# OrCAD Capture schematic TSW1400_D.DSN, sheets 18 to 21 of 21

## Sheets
18 FPGA Power: size B; title: FPGA Power
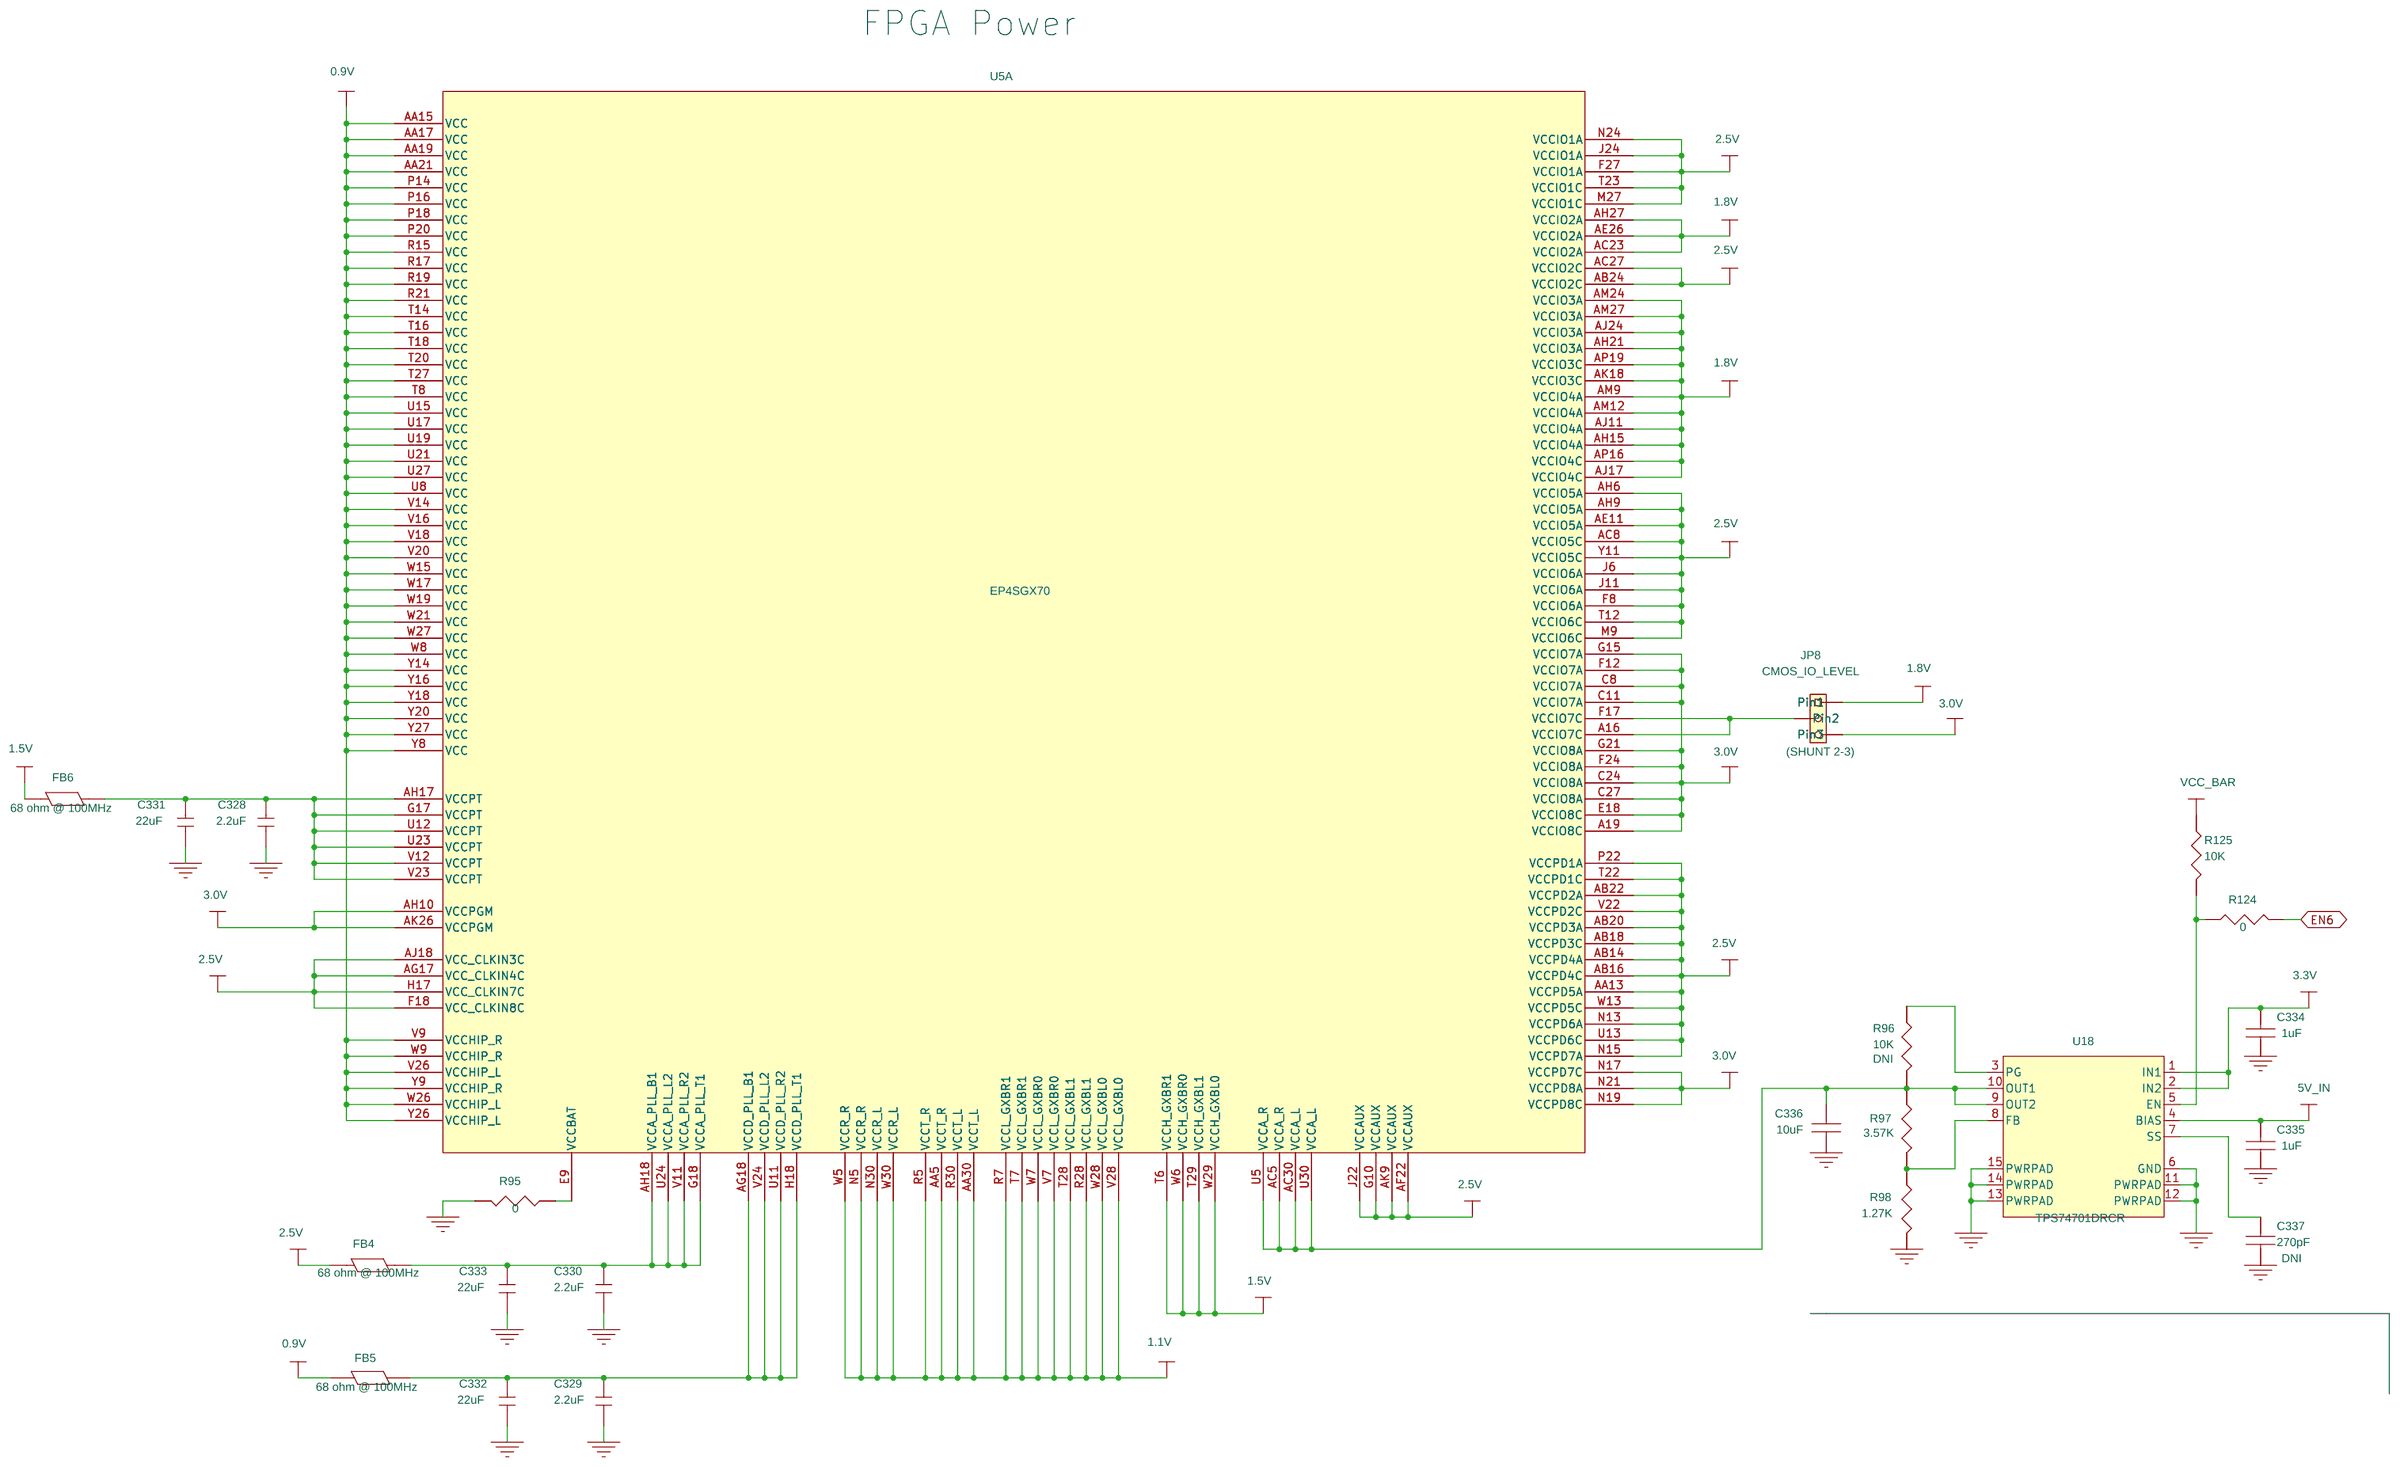
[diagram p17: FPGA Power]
19 FPGA Ground: size B; title: FPGA Ground
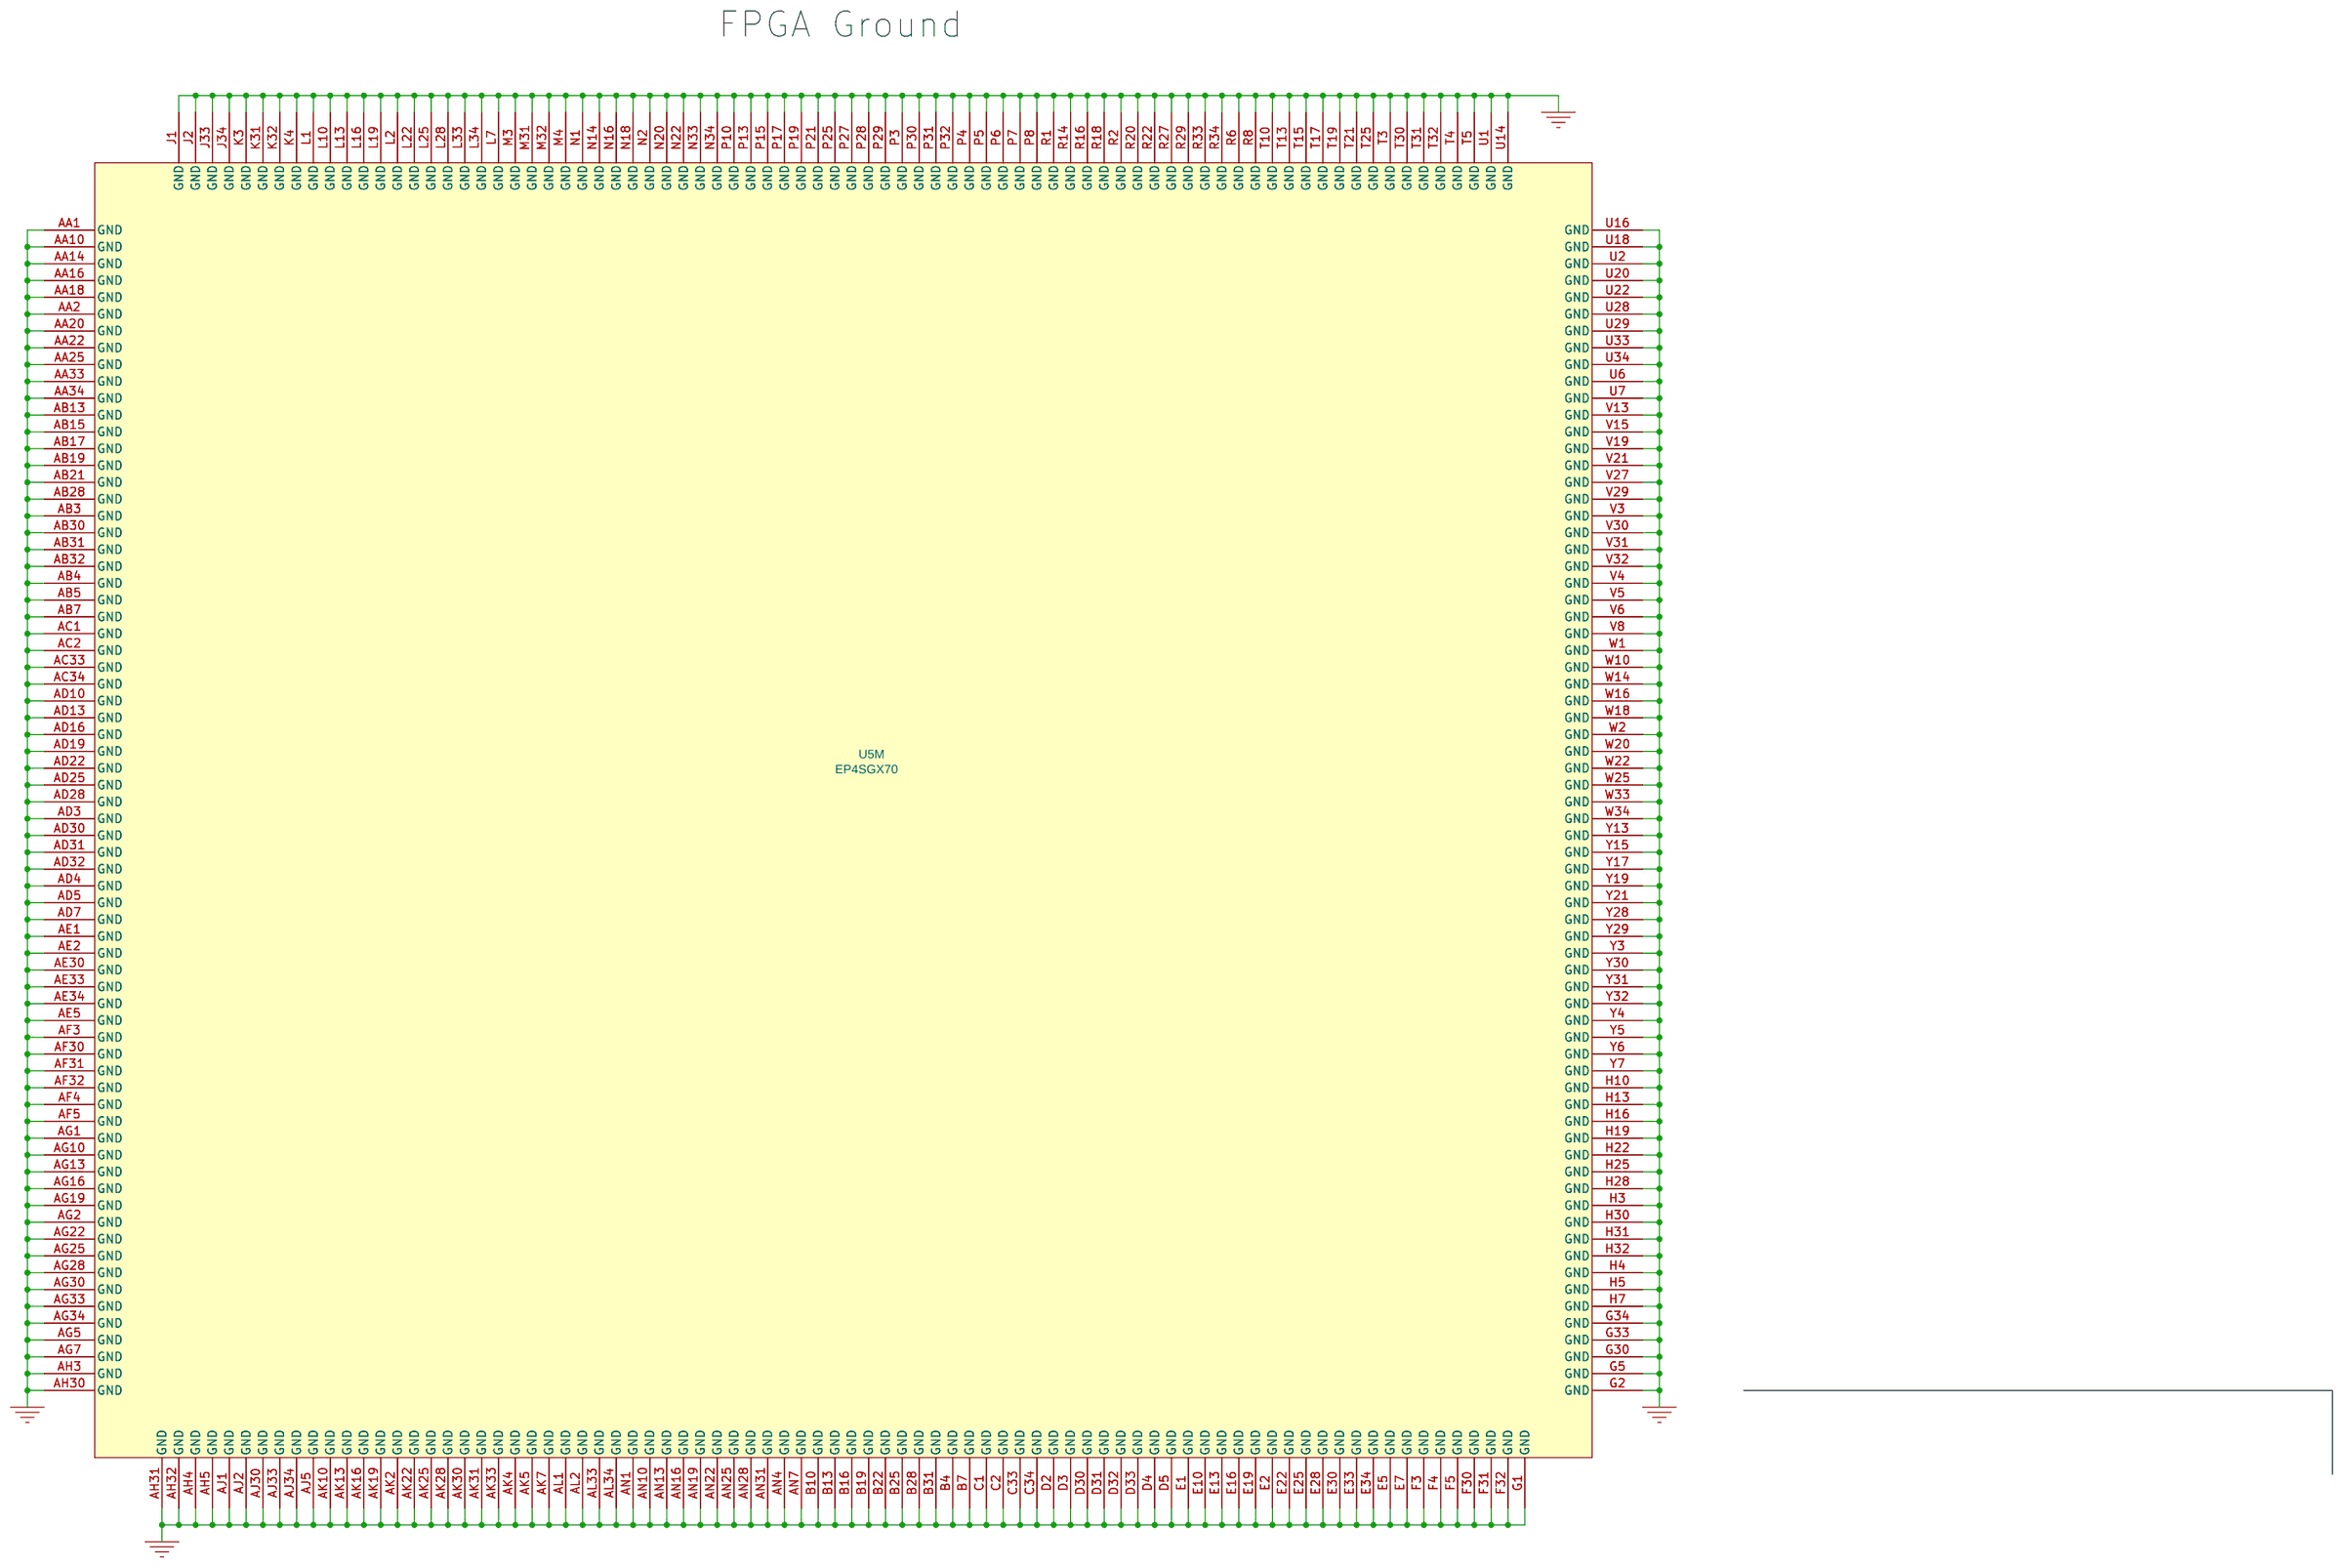
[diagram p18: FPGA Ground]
20 FPGA Decoupling: size B; title: FPGA Decoupling
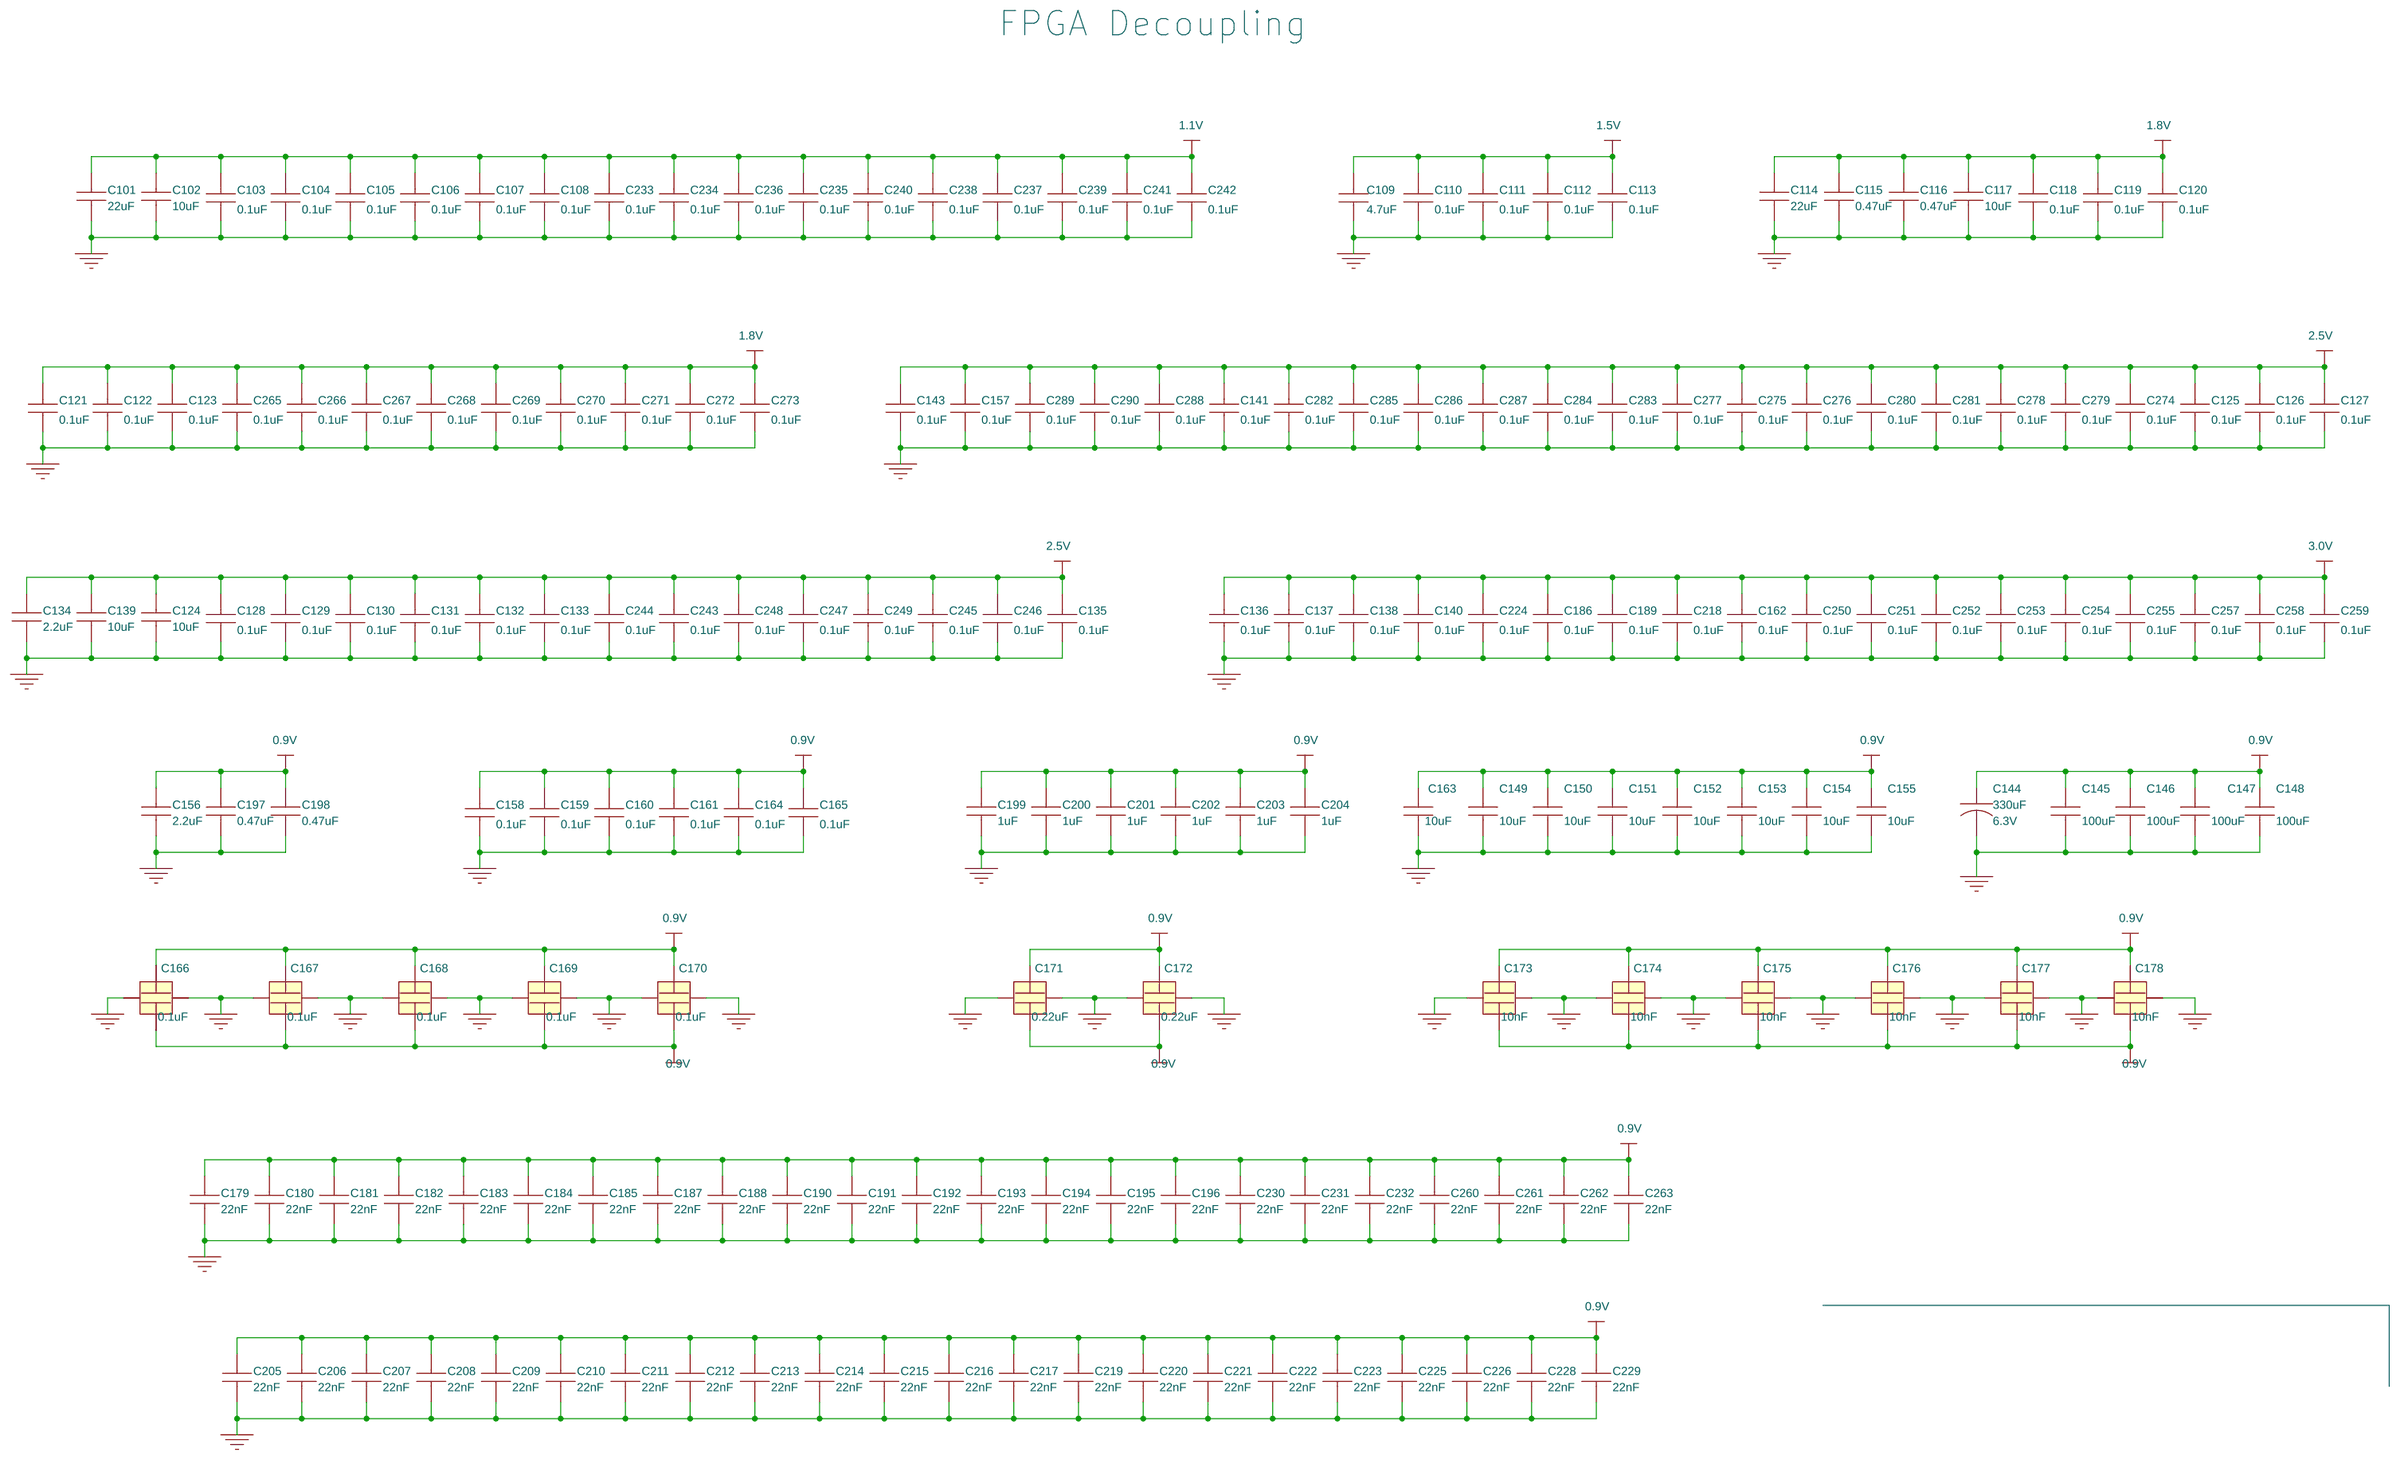
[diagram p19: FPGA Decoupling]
21 FPGA Configuration: size B; title: FPGA Configuration
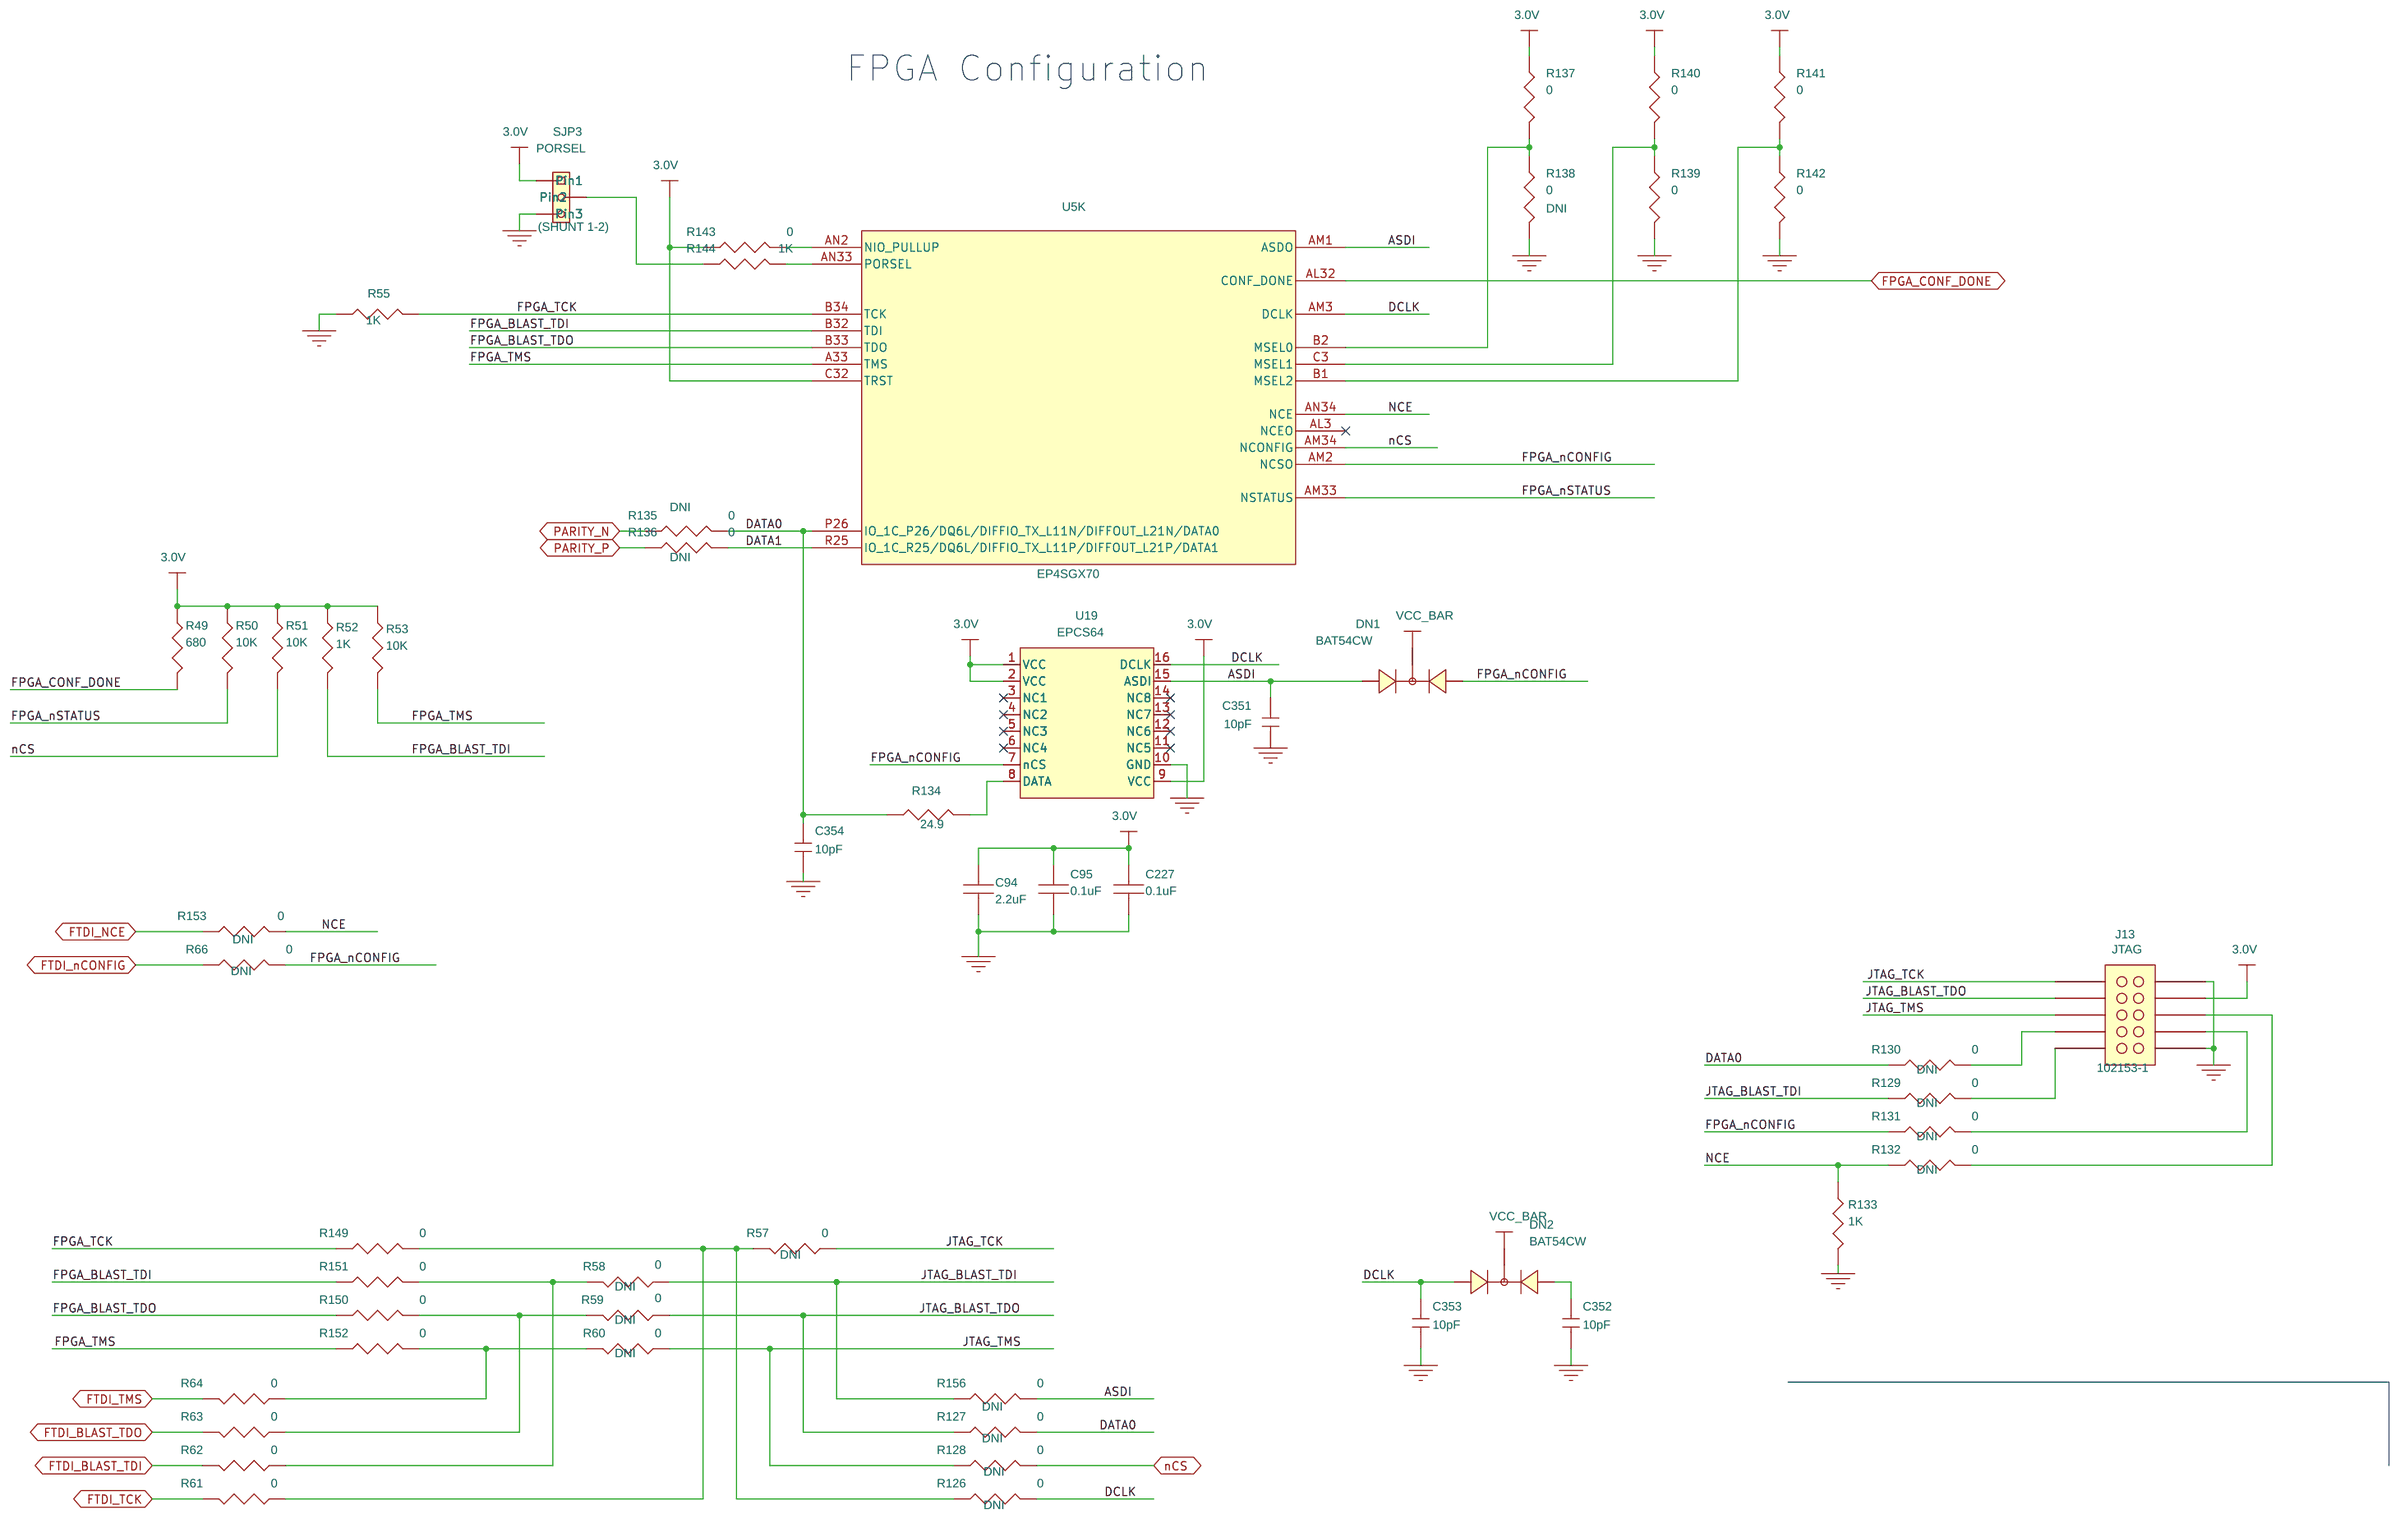
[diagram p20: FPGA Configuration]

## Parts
sheet Bank6
U5  EP4SGX70  [BGA_1152_39]  (sections A,B,C,D,E,F,G,H,I,J,K,L,M,N)
sheet FPGA Configuration
C94  2.2uF  [0603]
C95  0.1uF  [0402]
C227  0.1uF  [0402]
C351  10pF  [0402]
C352  10pF  [0402]
C353  10pF  [0402]
C354  10pF  [0402]
DN1  BAT54CW  [SOT_323]
DN2  BAT54CW  [SOT_323]
J13  102153-1  [CON_THVT_2x5_100_M]
R49  680  [0402]
R50  10K  [0402]
R51  10K  [0402]
R52  1K  [0402]
R53  10K  [0402]
R55  1K  [0402]
R57  0  [0402]
R58  0  [0402]
R59  0  [0402]
R60  0  [0402]
R61  0  [0402]
R62  0  [0402]
R63  0  [0402]
R64  0  [0402]
R66  0  [0402]
R126  0  [0402]
R127  0  [0402]
R128  0  [0402]
R129  0  [0402]
R130  0  [0402]
R131  0  [0402]
R132  0  [0402]
R133  1K  [0402]
R134  24.9  [0402]
R135  0  [0201]
R136  0  [0201]
R137  0  [0402]
R138  0  [0402]
R139  0  [0402]
R140  0  [0402]
R141  0  [0402]
R142  0  [0402]
R143  0  [0402]
R144  1K  [0402]
R149  0  [0402]
R150  0  [0402]
R151  0  [0402]
R152  0  [0402]
R153  0  [0402]
R156  0  [0402]
SJP3  SOLDER JUMPER, 0603  [SMD_JUMPER_1x3]
U19  EPCS64  [SOIC_16_410X299_50]
Z_SH-J3  SHUNT-JUMPER-0603  [0603]
sheet FPGA Decoupling
C101  22uF  [1210]
C102  10uF  [0603]
C103  0.1uF  [0201]
C104  0.1uF  [0201]
C105  0.1uF  [0201]
C106  0.1uF  [0201]
C107  0.1uF  [0201]
C108  0.1uF  [0201]
C109  4.7uF  [0603]
C110  0.1uF  [0201]
C111  0.1uF  [0201]
C112  0.1uF  [0201]
C113  0.1uF  [0201]
C114  22uF  [1210]
C115  0.47uF  [0402]
C116  0.47uF  [0402]
C117  10uF  [0603]
C118  0.1uF  [0201]
C119  0.1uF  [0201]
C120  0.1uF  [0201]
C121  0.1uF  [0201]
C122  0.1uF  [0201]
C123  0.1uF  [0201]
C124  10uF  [0603]
C125  0.1uF  [0201]
C126  0.1uF  [0201]
C127  0.1uF  [0201]
C128  0.1uF  [0201]
C129  0.1uF  [0201]
C130  0.1uF  [0201]
C131  0.1uF  [0201]
C132  0.1uF  [0201]
C133  0.1uF  [0201]
C134  2.2uF  [0603]
C135  0.1uF  [0201]
C136  0.1uF  [0201]
C137  0.1uF  [0201]
C138  0.1uF  [0201]
C139  10uF  [0603]
C140  0.1uF  [0201]
C141  0.1uF  [0201]
C143  0.1uF  [0201]
C144  330uF  [TANT_D]
C145  100uF  [1210]
C146  100uF  [1210]
C147  100uF  [1210]
C148  100uF  [1210]
C149  10uF  [0603]
C150  10uF  [0603]
C151  10uF  [0603]
C152  10uF  [0603]
C153  10uF  [0603]
C154  10uF  [0603]
C155  10uF  [0603]
C156  2.2uF  [0603]
C157  0.1uF  [0201]
C158  0.1uF  [0201]
C159  0.1uF  [0201]
C160  0.1uF  [0201]
C161  0.1uF  [0201]
C162  0.1uF  [0201]
C163  10uF  [0603]
C164  0.1uF  [0201]
C165  0.1uF  [0201]
C166  0.1uF  [C-0603_X2Y]
C167  0.1uF  [C-0603_X2Y]
C168  0.1uF  [C-0603_X2Y]
C169  0.1uF  [C-0603_X2Y]
C170  0.1uF  [C-0603_X2Y]
C171  0.22uF  [C-0603_X2Y]
C172  0.22uF  [C-0603_X2Y]
C173  10nF  [C-0603_X2Y]
C174  10nF  [C-0603_X2Y]
C175  10nF  [C-0603_X2Y]
C176  10nF  [C-0603_X2Y]
C177  10nF  [C-0603_X2Y]
C178  10nF  [C-0603_X2Y]
C179  22nF  [0201]
C180  22nF  [0201]
C181  22nF  [0201]
C182  22nF  [0201]
C183  22nF  [0201]
C184  22nF  [0201]
C185  22nF  [0201]
C186  0.1uF  [0201]
C187  22nF  [0201]
C188  22nF  [0201]
C189  0.1uF  [0201]
C190  22nF  [0201]
C191  22nF  [0201]
C192  22nF  [0201]
C193  22nF  [0201]
C194  22nF  [0201]
C195  22nF  [0201]
C196  22nF  [0201]
C197  0.47uF  [0402]
C198  0.47uF  [0402]
C199  1uF  [0402]
C200  1uF  [0402]
C201  1uF  [0402]
C202  1uF  [0402]
C203  1uF  [0402]
C204  1uF  [0402]
C205  22nF  [0201]
C206  22nF  [0201]
C207  22nF  [0201]
C208  22nF  [0201]
C209  22nF  [0201]
C210  22nF  [0201]
C211  22nF  [0201]
C212  22nF  [0201]
C213  22nF  [0201]
C214  22nF  [0201]
C215  22nF  [0201]
C216  22nF  [0201]
C217  22nF  [0201]
C218  0.1uF  [0201]
C219  22nF  [0201]
C220  22nF  [0201]
C221  22nF  [0201]
C222  22nF  [0201]
C223  22nF  [0201]
C224  0.1uF  [0201]
C225  22nF  [0201]
C226  22nF  [0201]
C228  22nF  [0201]
C229  22nF  [0201]
C230  22nF  [0201]
C231  22nF  [0201]
C232  22nF  [0201]
C233  0.1uF  [0201]
C234  0.1uF  [0201]
C235  0.1uF  [0201]
C236  0.1uF  [0201]
C237  0.1uF  [0201]
C238  0.1uF  [0201]
C239  0.1uF  [0201]
C240  0.1uF  [0201]
C241  0.1uF  [0201]
C242  0.1uF  [0201]
C243  0.1uF  [0201]
C244  0.1uF  [0201]
C245  0.1uF  [0201]
C246  0.1uF  [0201]
C247  0.1uF  [0201]
C248  0.1uF  [0201]
C249  0.1uF  [0201]
C250  0.1uF  [0201]
C251  0.1uF  [0201]
C252  0.1uF  [0201]
C253  0.1uF  [0201]
C254  0.1uF  [0201]
C255  0.1uF  [0201]
C257  0.1uF  [0201]
C258  0.1uF  [0201]
C259  0.1uF  [0201]
C260  22nF  [0201]
C261  22nF  [0201]
C262  22nF  [0201]
C263  22nF  [0201]
C265  0.1uF  [0201]
C266  0.1uF  [0201]
C267  0.1uF  [0201]
C268  0.1uF  [0201]
C269  0.1uF  [0201]
C270  0.1uF  [0201]
C271  0.1uF  [0201]
C272  0.1uF  [0201]
C273  0.1uF  [0201]
C274  0.1uF  [0201]
C275  0.1uF  [0201]
C276  0.1uF  [0201]
C277  0.1uF  [0201]
C278  0.1uF  [0201]
C279  0.1uF  [0201]
C280  0.1uF  [0201]
C281  0.1uF  [0201]
C282  0.1uF  [0201]
C283  0.1uF  [0201]
C284  0.1uF  [0201]
C285  0.1uF  [0201]
C286  0.1uF  [0201]
C287  0.1uF  [0201]
C288  0.1uF  [0201]
C289  0.1uF  [0201]
C290  0.1uF  [0201]
sheet FPGA Power
C328  2.2uF  [0402]
C329  2.2uF  [0402]
C330  2.2uF  [0402]
C331  22uF  [0603]
C332  22uF  [0603]
C333  22uF  [0603]
C334  1uF  [0603]
C335  1uF  [0603]
C336  10uF  [0603]
C337  270pF  [0603]
FB4  68 ohm @ 100MHz  [1206]
FB5  68 ohm @ 100MHz  [1206]
FB6  68 ohm @ 100MHz  [1206]
JP8  HEADER_1x3_100_430L  [HDR_THVT_1x3_100_M]
R95  0  [0402]
R96  10K  [0603]
R97  3.57K  [0603]
R98  1.27K  [0603]
R124  0  [0603]
R125  10K  [0603]
U18  TPS74701DRCR  [SON_10_124x124_pwrpad]
Z_SH-H3  SHUNT-HEADER

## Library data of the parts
U5 = EP4SGX70F1152_2
C94 C134 C156 = CAP: 2.2uF, +/-10%, 10V, X5R(0603); Mfr_Name: Yageo; Mfr_Part_Number: CC0603KRX5R6BB225; Package: SMD; Terasic_Prt: MCC-2000-YGO; Type: Capacitor
C95 C227 = CAP: Mfr_Name: Murata; Mfr_Part_Number: GRM155R61A104KA01D; Package: SMD; Type: Capacitor
C351-C354 = CAP_0402_10pF: Mfr_Name: Murata
DN1 DN2 = DIODE_DUAL_BAT54CW: Mfr_Name: Diodes Inc.
J13 = Header_2x5_100_1: Mfr_Name: Tyco; TI_SILKTEXT: JTAG
R49 = RES: Mfr_Name: Panasonic; Mfr_Part_Number: ERA-W27J681X; Type: Resistor
R50 R51 R53 = RES: Mfr_Name: Panasonic; Mfr_Part_Number: ERJ-2RKF1002X; Type: Resistor
R52 R55 R133 R144 = RES: Mfr_Name: Panasonic; Mfr_Part_Number: ERJ-2RKF1001X
R57-R60 R138 = Res_0402_Zero: Mfr_Name: Panasonic; Mfr_Part_Number: ERJ-2GE0R00X_DNI; Note: DNI
R61-R64 = Res_0402_Zero: Mfr_Name: Panasonic; Mfr_Part_Number: ERJ-2GE0R00X
R66 R126-R132 R153 R156 = Res_0402_Zero_H: Mfr_Name: Panasonic; Mfr_Part_Number: ERJ-2GE0R00X_DNI; Note: DNI
R134 = Res_0402_24.9_H: Mfr_Name: Panasonic
R135 R136 = Res_0402_Zero_H: Mfr_Name: Panasonic; Mfr_Part_Number: ERJ-1GE0R00C_DNI; Note: DNI
R137 = Res_0402_Zero_DNI: Mfr_Name: Panasonic; Mfr_Part_Number: ERJ-2GE0R00X
R139 R141 = Res_0402_Zero_DNI: Mfr_Name: Panasonic
R95 R140 R142 = Res_0402_Zero: Mfr_Name: Panasonic
R143 = Res_0402_Zero_H: Mfr_Name: Panasonic
R149-R152 = Res_0402_Zero_H: Mfr_Name: Panasonic; Mfr_Part_Number: ERJ-2GE0R00X
SJP3 = JUMPER_SMD_1X3: Note: (SHUNT 1-2); TI_Silktext: PORSEL
U19 = EPCS64: Mfr_Name: Altera
Z_SH-J3 = SHUNT-JUMPER-0603
C101 C114 = CAP: MLCC, 22uF, +/-10%, 10V, X5R(1210); Mfr_Name: Murata; Mfr_Part_Number: GRM32ER61A226KE20L; Package: SMD; Terasic_Prt: M1014; Type: Capacitor
C102 C117 C124 C139 C149-C155 C163 C336 = CAP: Mfr_Name: Murata; Mfr_Part_Number: GRM188R60J106ME47D; TOL: 20%; VOLTAGE: 6.3V
C103-C108 C110-C113 C118-C123 C125-C133 C135-C138 C140 C141 C143 C157-C162 C164 C165 C186 C189 C218 C224 C233-C255 C257-C259 C265-C290 = CAP: Mfr_Name: Murata; Mfr_Part_Number: GRM033R60J104KE19D; Package: SMD; Type: Capacitor
C109 = CAP_NP_0: Mfr_Name: Kemet; Mfr_Part_Number: C0603C475K8PACTU; TOL: 10%; VOLTAGE: 10V
C115 C116 C197 C198 = CAP: Mfr_Name: Murata; Mfr_Part_Number: GRM155F51A474ZE01D
C144 = CAPT: Mfr_Name: Kemet; Mfr_Part_Number: T520D337M006ATE015; Package: SMD; Voltage: 6.3V
C145-C148 = CAP: Mfr_Name: Murata; Mfr_Part_Number: GRM32ER60J107ME20L; TOL: 20%; VOLTAGE: 6.3V
C166-C170 = CAP_X2Y: Mfr_Name: Johanson Dielectrics Inc; Mfr_Part_Number: 100X14W104MV4T; Package: SMD; Type: Capacitor
C171 C172 = CAP_X2Y: X2Y, 0.22uF, +/-20%, 10V, X5R(0603); Mfr_Name: Johanson Dielectrics Inc; Mfr_Part_Number: 160X14X224MV4T; Package: SMD; Terasic_Prt: MP03-16112R; Type: Capacitor
C173-C178 = CAP_X2Y: X2Y, 10nF, +/-20%, 50V, X7R, 0603; Mfr_Name: Johanson Dielectrics Inc; Mfr_Part_Number: 500X14W103MV4T; Package: SMD; Terasic_Prt: M1099; Type: Capacitor
C179-C185 C187 C188 C190-C196 C205-C217 C219-C223 C225 C226 C228-C232 C260-C263 = CAP: Mfr_Name: Murata; Mfr_Part_Number: GRM033R60J223KE01D
C199-C204 = CAP: Mfr_Name: Murata; Mfr_Part_Number: GRM155R61A105KE15D; Tolerance: 10%; Voltage: 10V
C328-C330 = CAP0201: Mfr_Name: Taiyo Yuden; Mfr_Part_Number: JMK105BJ225MV-F; TOL: 20%; VOLTAGE: 6.3V
C331-C333 = CAP0201: Mfr_Name: Taiyo Yuden; Mfr_Part_Number: AMK107BJ226MA-T; TOL: 20%; VOLTAGE: 4V
C334 C335 = CAP_0603_H: Mfr_Name: Murata; Mfr_Part_Number: GRM188R60J105KA01D; Tolerance: 10%; Voltage: 6.3V
C337 = CAP: Mfr_Name: Murata; Mfr_Part_Number: GRM1885C1H271JA01D_DNI; Note: DNI
FB4-FB6 = FERRITE_BEAD: Mfr_Name: Panasonic; Mfr_Part_Number: EXC-ML32A680U
JP8 = JUMPER_1x3_100: Note: (SHUNT 2-3); TI_Silktext: CMOS_IO_LEVEL
R96 = RES: Mfr_Name: Panasonic; Mfr_Part_Number: ERJ-3EKF1002V_DNI; Note: DNI; Type: Resistor
R97 = RES: Mfr_Name: Panasonic; Mfr_Part_Number: ERJ-3EKF3571V; Type: Resistor
R98 = RES: Mfr_Name: Panasonic; Mfr_Part_Number: ERJ-3EKF1271V; Type: Resistor
R124 = RES: Mfr_Name: Panasonic; Mfr_Part_Number: ERJ-3GEY0R00V; Type: Resistor
R125 = Res_0603_10k: Mfr_Name: Panasonic
U18 = TPS74701DRCR
Z_SH-H3 = SHUNT-3PINHEADER

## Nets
0.9V: C144.1(ANODE) C145.1 C146.1 C147.1 C148.1 C149.1 C150.1 C151.1 C152.1 C153.1 C154.1 C155.1 C156.1 C158.2 C159.2 C160.2 C161.2 C163.1 C164.2 C165.2 C166.A C166.B C167.A C167.B C168.A C168.B C169.A C169.B C170.A C170.B C171.A C171.B C172.A C172.B C173.A C173.B C174.A C174.B C175.A C175.B C176.A C176.B C177.A C177.B C178.A C178.B C179.1 C180.1 C181.1 C182.1 C183.1 C184.1 C185.1 C187.1 C188.1 C190.1 C191.1 C192.1 C193.1 C194.1 C195.1 C196.1 C197.1 C198.1 C199.1 C200.1 C201.1 C202.1 C203.1 C204.1 C205.1 C206.1 C207.1 C208.1 C209.1 C210.1 C211.1 C212.1 C213.1 C214.1 C215.1 C216.1 C217.1 C219.1 C220.1 C221.1 C222.1 C223.1 C225.1 C226.1 C228.1 C229.1 C230.1 C231.1 C232.1 C260.1 C261.1 C262.1 C263.1 FB5.1 U5.AA15(VCC) U5.AA17(VCC) U5.AA19(VCC) U5.AA21(VCC) U5.P14(VCC) U5.P16(VCC) U5.P18(VCC) U5.P20(VCC) U5.R15(VCC) U5.R17(VCC) U5.R19(VCC) U5.R21(VCC) U5.T8(VCC) U5.T14(VCC) U5.T16(VCC) U5.T18(VCC) U5.T20(VCC) U5.T27(VCC) U5.U8(VCC) U5.U15(VCC) U5.U17(VCC) U5.U19(VCC) U5.U21(VCC) U5.U27(VCC) U5.V9(VCCHIP_R) U5.V14(VCC) U5.V16(VCC) U5.V18(VCC) U5.V20(VCC) U5.V26(VCCHIP_L) U5.W8(VCC) U5.W9(VCCHIP_R) U5.W15(VCC) U5.W17(VCC) U5.W19(VCC) U5.W21(VCC) U5.W26(VCCHIP_L) U5.W27(VCC) U5.Y8(VCC) U5.Y9(VCCHIP_R) U5.Y14(VCC) U5.Y16(VCC) U5.Y18(VCC) U5.Y20(VCC) U5.Y26(VCCHIP_L) U5.Y27(VCC) ; also on sheet 7 16
1.1V: C101.1 C102.1 C103.2 C104.2 C105.2 C106.2 C107.2 C108.2 C233.2 C234.2 C235.2 C236.2 C237.2 C238.2 C239.2 C240.2 C241.2 C242.2 U5.AA5(VCCT_R) U5.AA30(VCCT_L) U5.N5(VCCR_R) U5.N30(VCCR_L) U5.R5(VCCT_R) U5.R7(VCCL_GXBR1) U5.R28(VCCL_GXBL1) U5.R30(VCCT_L) U5.T7(VCCL_GXBR1) U5.T28(VCCL_GXBL1) U5.V7(VCCL_GXBR0) U5.V28(VCCL_GXBL0) U5.W5(VCCR_R) U5.W7(VCCL_GXBR0) U5.W28(VCCL_GXBL0) U5.W30(VCCR_L) ; also on sheet 16
1.5V: C109.2 C110.2 C111.2 C112.2 C113.2 FB6.1 U5.T6(VCCH_GXBR1) U5.T29(VCCH_GXBL1) U5.W6(VCCH_GXBR0) U5.W29(VCCH_GXBL0) ; also on sheet 16
1.8V: C114.1 C115.1 C116.1 C117.1 C118.2 C119.2 C120.2 C121.2 C122.2 C123.2 C265.2 C266.2 C267.2 C268.2 C269.2 C270.2 C271.2 C272.2 C273.2 JP8.1(Pin1) U5.AC23(VCCIO2A) U5.AE26(VCCIO2A) U5.AH15(VCCIO4A) U5.AH21(VCCIO3A) U5.AH27(VCCIO2A) U5.AJ11(VCCIO4A) U5.AJ17(VCCIO4C) U5.AJ24(VCCIO3A) U5.AK18(VCCIO3C) U5.AM9(VCCIO4A) U5.AM12(VCCIO4A) U5.AM24(VCCIO3A) U5.AM27(VCCIO3A) U5.AP16(VCCIO4C) U5.AP19(VCCIO3C) ; also on sheet 5 6 9 16
2.5V: C124.1 C125.2 C126.2 C127.2 C128.2 C129.2 C130.2 C131.2 C132.2 C133.2 C134.1 C135.2 C139.1 C141.2 C143.2 C157.2 C243.2 C244.2 C245.2 C246.2 C247.2 C248.2 C249.2 C274.2 C275.2 C276.2 C277.2 C278.2 C279.2 C280.2 C281.2 C282.2 C283.2 C284.2 C285.2 C286.2 C287.2 C288.2 C289.2 C290.2 FB4.1 U5.AA13(VCCPD5A) U5.AB14(VCCPD4A) U5.AB16(VCCPD4C) U5.AB18(VCCPD3C) U5.AB20(VCCPD3A) U5.AB22(VCCPD2A) U5.AB24(VCCIO2C) U5.AC8(VCCIO5C) U5.AC27(VCCIO2C) U5.AE11(VCCIO5A) U5.AF22(VCCAUX) U5.AG17(VCC_CLKIN4C) U5.AH6(VCCIO5A) U5.AH9(VCCIO5A) U5.AJ18(VCC_CLKIN3C) U5.AK9(VCCAUX) U5.F8(VCCIO6A) U5.F18(VCC_CLKIN8C) U5.F27(VCCIO1A) U5.G10(VCCAUX) U5.H17(VCC_CLKIN7C) U5.J6(VCCIO6A) U5.J11(VCCIO6A) U5.J22(VCCAUX) U5.J24(VCCIO1A) U5.M9(VCCIO6C) U5.M27(VCCIO1C) U5.N13(VCCPD6A) U5.N15(VCCPD7A) U5.N24(VCCIO1A) U5.P22(VCCPD1A) U5.T12(VCCIO6C) U5.T22(VCCPD1C) U5.T23(VCCIO1C) U5.U13(VCCPD6C) U5.V22(VCCPD2C) U5.W13(VCCPD5C) U5.Y11(VCCIO5C) ; also on sheet 16 17
3.0V: C94.1 C95.1 C136.2 C137.2 C138.2 C140.2 C162.2 C186.2 C189.2 C218.2 C224.2 C227.1 C250.2 C251.2 C252.2 C253.2 C254.2 C255.2 C257.2 C258.2 C259.2 DN1.3 DN2.3 J13.4 JP8.3(Pin3) R49.1 R50.1 R51.1 R52.2 R53.1 R137.1 R140.1 R141.1 R143.1 SJP3.1(Pin1) U5.A19(VCCIO8C) U5.AH10(VCCPGM) U5.AK26(VCCPGM) U5.C8(VCCIO7A) U5.C11(VCCIO7A) U5.C24(VCCIO8A) U5.C27(VCCIO8A) U5.C32(TRST) U5.E18(VCCIO8C) U5.F12(VCCIO7A) U5.F24(VCCIO8A) U5.G15(VCCIO7A) U5.G21(VCCIO8A) U5.N17(VCCPD7C) U5.N19(VCCPD8C) U5.N21(VCCPD8A) U19.1(VCC) U19.2(VCC) U19.9(VCC) ; also on sheet 5 17
3.3V: C334.2 R125.1 U18.1(IN1) U18.2(IN2) ; also on sheet 1 7 17
5V_IN: C335.2 U18.4(BIAS) ; also on sheet 1 16 17
GND: C94.2 C95.2 C101.2 C102.2 C103.1 C104.1 C105.1 C106.1 C107.1 C108.1 C109.1 C110.1 C111.1 C112.1 C113.1 C114.2 C115.2 C116.2 C117.2 C118.1 C119.1 C120.1 C121.1 C122.1 C123.1 C124.2 C125.1 C126.1 C127.1 C128.1 C129.1 C130.1 C131.1 C132.1 C133.1 C134.2 C135.1 C136.1 C137.1 C138.1 C139.2 C140.1 C141.1 C143.1 C144.2(CATHODE) C145.2 C146.2 C147.2 C148.2 C149.2 C150.2 C151.2 C152.2 C153.2 C154.2 C155.2 C156.2 C157.1 C158.1 C159.1 C160.1 C161.1 C162.1 C163.2 C164.1 C165.1 C166.G1 C166.G2 C167.G1 C167.G2 C168.G1 C168.G2 C169.G1 C169.G2 C170.G1 C170.G2 C171.G1 C171.G2 C172.G1 C172.G2 C173.G1 C173.G2 C174.G1 C174.G2 C175.G1 C175.G2 C176.G1 C176.G2 C177.G1 C177.G2 C178.G1 C178.G2 C179.2 C180.2 C181.2 C182.2 C183.2 C184.2 C185.2 C186.1 C187.2 C188.2 C189.1 C190.2 C191.2 C192.2 C193.2 C194.2 C195.2 C196.2 C197.2 C198.2 C199.2 C200.2 C201.2 C202.2 C203.2 C204.2 C205.2 C206.2 C207.2 C208.2 C209.2 C210.2 C211.2 C212.2 C213.2 C214.2 C215.2 C216.2 C217.2 C218.1 C219.2 C220.2 C221.2 C222.2 C223.2 C224.1 C225.2 C226.2 C227.2 C228.2 C229.2 C230.2 C231.2 C232.2 C233.1 C234.1 C235.1 C236.1 C237.1 C238.1 C239.1 C240.1 C241.1 C242.1 C243.1 C244.1 C245.1 C246.1 C247.1 C248.1 C249.1 C250.1 C251.1 C252.1 C253.1 C254.1 C255.1 C257.1 C258.1 C259.1 C260.2 C261.2 C262.2 C263.2 C265.1 C266.1 C267.1 C268.1 C269.1 C270.1 C271.1 C272.1 C273.1 C274.1 C275.1 C276.1 C277.1 C278.1 C279.1 C280.1 C281.1 C282.1 C283.1 C284.1 C285.1 C286.1 C287.1 C288.1 C289.1 C290.1 C328.2 C329.2 C330.2 C331.2 C332.2 C333.2 C334.1 C335.1 C336.2 C337.2 C351.2 C352.2 C353.2 C354.2 J13.2 J13.10 R55.1 R95.2 R98.1 R133.2 R138.2 R139.2 R142.2 SJP3.3(Pin3) U5.AA1(GND) U5.AA2(GND) U5.AA10(GND) U5.AA14(GND) U5.AA16(GND) U5.AA18(GND) U5.AA20(GND) U5.AA22(GND) U5.AA25(GND) U5.AA33(GND) U5.AA34(GND) U5.AB3(GND) U5.AB4(GND) U5.AB5(GND) U5.AB7(GND) U5.AB13(GND) U5.AB15(GND) U5.AB17(GND) U5.AB19(GND) U5.AB21(GND) U5.AB28(GND) U5.AB30(GND) U5.AB31(GND) U5.AB32(GND) U5.AC1(GND) U5.AC2(GND) U5.AC33(GND) U5.AC34(GND) U5.AD3(GND) U5.AD4(GND) U5.AD5(GND) U5.AD7(GND) U5.AD10(GND) U5.AD13(GND) U5.AD16(GND) U5.AD19(GND) U5.AD22(GND) U5.AD25(GND) U5.AD28(GND) U5.AD30(GND) U5.AD31(GND) U5.AD32(GND) U5.AE1(GND) U5.AE2(GND) U5.AE5(GND) U5.AE30(GND) U5.AE33(GND) U5.AE34(GND) U5.AF3(GND) U5.AF4(GND) U5.AF5(GND) U5.AF30(GND) U5.AF31(GND) U5.AF32(GND) U5.AG1(GND) U5.AG2(GND) U5.AG5(GND) U5.AG7(GND) U5.AG10(GND) U5.AG13(GND) U5.AG16(GND) U5.AG19(GND) U5.AG22(GND) U5.AG25(GND) U5.AG28(GND) U5.AG30(GND) U5.AG33(GND) U5.AG34(GND) U5.AH3(GND) U5.AH4(GND) U5.AH5(GND) U5.AH30(GND) U5.AH31(GND) U5.AH32(GND) U5.AJ1(GND) U5.AJ2(GND) U5.AJ5(GND) U5.AJ30(GND) U5.AJ33(GND) U5.AJ34(GND) U5.AK2(GND) U5.AK4(GND) U5.AK5(GND) U5.AK7(GND) U5.AK10(GND) U5.AK13(GND) U5.AK16(GND) U5.AK19(GND) U5.AK22(GND) U5.AK25(GND) U5.AK28(GND) U5.AK30(GND) U5.AK31(GND) U5.AK33(GND) U5.AL1(GND) U5.AL2(GND) U5.AL33(GND) U5.AL34(GND) U5.AN1(GND) U5.AN4(GND) U5.AN7(GND) U5.AN10(GND) U5.AN13(GND) U5.AN16(GND) U5.AN19(GND) U5.AN22(GND) U5.AN25(GND) U5.AN28(GND) U5.AN31(GND) U5.B4(GND) U5.B7(GND) U5.B10(GND) U5.B13(GND) U5.B16(GND) U5.B19(GND) U5.B22(GND) U5.B25(GND) U5.B28(GND) U5.B31(GND) U5.C1(GND) U5.C2(GND) U5.C33(GND) U5.C34(GND) U5.D2(GND) U5.D3(GND) U5.D4(GND) U5.D5(GND) U5.D30(GND) U5.D31(GND) U5.D32(GND) U5.D33(GND) U5.E1(GND) U5.E2(GND) U5.E5(GND) U5.E7(GND) U5.E10(GND) U5.E13(GND) U5.E16(GND) U5.E19(GND) U5.E22(GND) U5.E25(GND) U5.E28(GND) U5.E30(GND) U5.E33(GND) U5.E34(GND) U5.F3(GND) U5.F4(GND) U5.F5(GND) U5.F30(GND) U5.F31(GND) U5.F32(GND) U5.G1(GND) U5.G2(GND) U5.G5(GND) U5.G30(GND) U5.G33(GND) U5.G34(GND) U5.H3(GND) U5.H4(GND) U5.H5(GND) U5.H7(GND) U5.H10(GND) U5.H13(GND) U5.H16(GND) U5.H19(GND) U5.H22(GND) U5.H25(GND) U5.H28(GND) U5.H30(GND) U5.H31(GND) U5.H32(GND) U5.J1(GND) U5.J2(GND) U5.J33(GND) U5.J34(GND) U5.K3(GND) U5.K4(GND) U5.K31(GND) U5.K32(GND) U5.L1(GND) U5.L2(GND) U5.L7(GND) U5.L10(GND) U5.L13(GND) U5.L16(GND) U5.L19(GND) U5.L22(GND) U5.L25(GND) U5.L28(GND) U5.L33(GND) U5.L34(GND) U5.M3(GND) U5.M4(GND) U5.M31(GND) U5.M32(GND) U5.N1(GND) U5.N2(GND) U5.N14(GND) U5.N16(GND) U5.N18(GND) U5.N20(GND) U5.N22(GND) U5.N33(GND) U5.N34(GND) U5.P3(GND) U5.P4(GND) U5.P5(GND) U5.P6(GND) U5.P7(GND) U5.P8(GND) U5.P10(GND) U5.P13(GND) U5.P15(GND) U5.P17(GND) U5.P19(GND) U5.P21(GND) U5.P25(GND) U5.P27(GND) U5.P28(GND) U5.P29(GND) U5.P30(GND) U5.P31(GND) U5.P32(GND) U5.R1(GND) U5.R2(GND) U5.R6(GND) U5.R8(GND) U5.R14(GND) U5.R16(GND) U5.R18(GND) U5.R20(GND) U5.R22(GND) U5.R27(GND) U5.R29(GND) U5.R33(GND) U5.R34(GND) U5.T3(GND) U5.T4(GND) U5.T5(GND) U5.T10(GND) U5.T13(GND) U5.T15(GND) U5.T17(GND) U5.T19(GND) U5.T21(GND) U5.T25(GND) U5.T30(GND) U5.T31(GND) U5.T32(GND) U5.U1(GND) U5.U2(GND) U5.U6(GND) U5.U7(GND) U5.U14(GND) U5.U16(GND) U5.U18(GND) U5.U20(GND) U5.U22(GND) U5.U28(GND) U5.U29(GND) U5.U33(GND) U5.U34(GND) U5.V3(GND) U5.V4(GND) U5.V5(GND) U5.V6(GND) U5.V8(GND) U5.V13(GND) U5.V15(GND) U5.V19(GND) U5.V21(GND) U5.V27(GND) U5.V29(GND) U5.V30(GND) U5.V31(GND) U5.V32(GND) U5.W1(GND) U5.W2(GND) U5.W10(GND) U5.W14(GND) U5.W16(GND) U5.W18(GND) U5.W20(GND) U5.W22(GND) U5.W25(GND) U5.W33(GND) U5.W34(GND) U5.Y3(GND) U5.Y4(GND) U5.Y5(GND) U5.Y6(GND) U5.Y7(GND) U5.Y13(GND) U5.Y15(GND) U5.Y17(GND) U5.Y19(GND) U5.Y21(GND) U5.Y28(GND) U5.Y29(GND) U5.Y30(GND) U5.Y31(GND) U5.Y32(GND) U18.6(GND) U18.11(PWRPAD) U18.12(PWRPAD) U18.13(PWRPAD) U18.14(PWRPAD) U18.15(PWRPAD) U19.10(GND) ; also on sheet 1 2 3 4 5 6 7 9 14 15 16 17
ASDI: C351.1 DN1.2 R156.2 U5.AM1(ASDO) U19.15(ASDI)
DATA0: C354.1 R127.2 R130.1 R134.1 R135.2 U5.P26(IO_1C_P26/DQ6L/DIFFIO_TX_L11N/DIFFOUT_L21N/DATA0)
DATA1: R136.2 U5.R25(IO_1C_R25/DQ6L/DIFFIO_TX_L11P/DIFFOUT_L21P/DATA1)
DCLK: C353.1 DN2.1 R126.2 U5.AM3(DCLK) U19.16(DCLK)
EN6: R124.2 ; also on sheet 1
FPGA_BLAST_TDI: R52.1 R151.1 U5.B32(TDI)
FPGA_BLAST_TDO: R150.1 U5.B33(TDO)
FPGA_CONF_DONE: R49.2 U5.AL32(CONF_DONE) ; also on sheet 1
FPGA_nCONFIG: DN1.1 R66.2 R131.1 U5.AM2(NCSO) U19.7(nCS)
FPGA_nSTATUS: R50.2 U5.AM33(NSTATUS)
FPGA_TCK: R55.2 R149.1 U5.B34(TCK)
FPGA_TMS: R53.2 R152.1 U5.A33(TMS)
FTDI_BLAST_TDI: R62.2 ; also on sheet 5
FTDI_BLAST_TDO: R63.2 ; also on sheet 5
FTDI_NCE: R153.1 ; also on sheet 5
FTDI_nCONFIG: R66.1 ; also on sheet 5
FTDI_TCK: R61.2 ; also on sheet 5
FTDI_TMS: R64.2 ; also on sheet 5
JTAG_BLAST_TDI: R58.1 R129.1 R156.1
JTAG_BLAST_TDO: J13.3 R59.1 R127.1
JTAG_TCK: J13.1 R57.1
JTAG_TMS: J13.5 R60.1 R128.1
NCE: R132.1 R133.1 R153.2 U5.AN34(NCE)
nCS: R51.2 R128.2 U5.AM34(NCONFIG) ; also on sheet 1
PARITY_N: R135.1 ; also on sheet 4
PARITY_P: R136.1 ; also on sheet 4
N16774346: C328.1 C331.1 FB6.2 U5.AH17(VCCPT) U5.G17(VCCPT) U5.U12(VCCPT) U5.U23(VCCPT) U5.V12(VCCPT) U5.V23(VCCPT)
N26521020: R59.2 R63.1 R150.2
N26523726: R58.2 R62.1 R151.2
N26526427: R57.2 R61.1 R126.1 R149.2
N26529134: R60.2 R64.1 R152.2
N35298740: C329.1 C332.1 FB5.2 U5.AG18(VCCD_PLL_B1) U5.H18(VCCD_PLL_T1) U5.U11(VCCD_PLL_R2) U5.V24(VCCD_PLL_L2)
N35303144: C330.1 C333.1 FB4.2 U5.AH18(VCCA_PLL_B1) U5.G18(VCCA_PLL_T1) U5.U24(VCCA_PLL_L2) U5.V11(VCCA_PLL_R2)
N35337600: C336.1 R96.1 R97.2 U5.AC5(VCCA_R) U5.AC30(VCCA_L) U5.U5(VCCA_R) U5.U30(VCCA_L) U18.9(OUT2) U18.10(OUT1)
N44426490: R124.1 R125.2 U18.5(EN)
N44456154: R96.2 U18.3(PG)
N44466162: R97.1 R98.2 U18.8(FB)
N44506277: C337.1 U18.7(SS)
N44658612: R95.1 U5.E9(VCCBAT)
N45543111: J13.9 R129.2
N45543118: J13.7 R130.2
N45543130: J13.8 R131.2
N45543159: J13.6 R132.2
N45543649: C352.1 DN2.2
N45629411: R137.2 R138.1 U5.B2(MSEL0)
N45629497: R139.1 R140.2 U5.C3(MSEL1)
N45629519: R141.2 R142.1 U5.B1(MSEL2)
N45638501: R134.2 U19.8(DATA)
N45782435: R143.2 U5.AN2(NIO_PULLUP)
N45836337: JP8.2(Pin2) U5.A16(VCCIO7C) U5.F17(VCCIO7C)
N45842530: R144.2 SJP3.2(Pin2)
N45845005: R144.1 U5.AN33(PORSEL)

Not connected (* = marked no-connect by the designer): U5 AL3(NCEO)*; U19 3(NC1)* 4(NC2)* 5(NC3)* 6(NC4)* 11(NC5)* 12(NC6)* 13(NC7)* 14(NC8)*

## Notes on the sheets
sheet 18
- FPGA Power
sheet 19
- FPGA Ground
sheet 20
- FPGA Decoupling
sheet 21
- FPGA Configuration
